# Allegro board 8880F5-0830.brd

Outline 581.66 x 429.26 mm; copper layers: TOP, L02_DGND, L03_SIGNAL, L04_DGND, L05_SIGNAL, L06_DGND, L07_SIGNAL, L08_DGND, L09_SIGNAL, L10_DGND, L11_POWER, L12_DGND, L13_POWER, L14_DGND, L15_POWER, L16_DGND, L17_5V, L18_CBIT, L19_DGND, L20_POWER, L21_DGND, L22_POWER, L23_DGND, L24_POWER, L25_DGND, L26_SIGNAL, L27_DGND, L28_SIGNAL, L29_DGND, L30_SIGNAL, L31_DGND, L32_SIGNAL, L33_DGND, BOTTOM. Coordinates in mm from the lower left corner of the outline.

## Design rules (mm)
net group DIFFPAIR0: nets D31702 D31704
net group DIFFPAIR1: nets D31706 D31708
net group DIFFPAIR2: nets D31710 D31712
net group DIFFPAIR3: nets D31714 D31716
net group DIFFPAIR4: nets D32102 D32104
net group DIFFPAIR5: nets D32106 D32108
net group DIFFPAIR6: nets D32110 D32112
net group DIFFPAIR7: nets D32114 D32116
net group DIFFPAIR8: nets D30102 D30104
net group DIFFPAIR9: nets D30106 D30108
net group DIFFPAIR10: nets D30110 D30112
net group DIFFPAIR11: nets D30114 D30116
net group DIFFPAIR12: nets D30502 D30504
net group DIFFPAIR13: nets D30506 D30508
net group DIFFPAIR14: nets D30510 D30512
net group DIFFPAIR15: nets D30514 D30516

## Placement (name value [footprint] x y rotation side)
BD29  BD120-3A-S8  [FB0805]  129.54 134.62 180 bottom
BD30  BD120-3A-S8  [FB0805]  129.54 146.05 180 bottom
BD31  BD120-3A-S8  [FB0805]  129.54 142.24 0 bottom
BD32  BD120-3A-S8  [FB0805]  513.08 238.76 180 bottom
BD33  BD120-3A-S8  [FB0805]  513.08 242.57 180 bottom
BD34  BD120-3A-S8  [FB0805]  453.64 145.54 0 bottom
BD35  BD120-3A-S8  [FB0805]  453.64 137.92 180 bottom
BD36  BD120-3A-S8  [FB0805]  129.54 138.43 180 bottom
BD37  BD120-3A-S8  [FB0805]  453.64 130.3 180 bottom
BD38  BD120-3A-S8  [FB0805]  513.08 242.57 180 bottom
BD39  BD120-3A-S8  [FB0805]  453.64 141.73 0 bottom
BD40  BD120-3A-S8  [FB0805]  453.64 134.11 180 bottom
BD41  BD120-3A-S8  [FB0805]  513.08 234.95 180 bottom
BD42  BD120-3A-S8  [FB0805]  513.08 231.14 180 bottom
BD43  BD120-3A-S8  [FB0805]  513.08 227.33 180 bottom
BD44  BD120-3A-S8  [FB0805]  129.54 149.86 180 bottom
BR902  330-1-S4  [R0402]  36.83 133.35 270 bottom
C3  0.1U-16-X-S4-MU  [C0402]  184.15 132.33 180 bottom
C4  0.1U-16-X-S4-MU  [C0402]  181.61 132.33 180 bottom
C5  22P-50-N-S4-AVX  [C0402]  221.21 277.48 90 bottom
C6  22P-50-N-S4-AVX  [C0402]  221.21 271.16 270 bottom
C7  0.1U-16-X-S4-MU  [C0402]  110.74 230.12 0 bottom
C8  0.1U-16-X-S4-MU  [C0402]  104.14 215.5 180 bottom
C9  0.1U-16-X-S4-MU  [C0402]  104.24 229.1 180 bottom
CA1  NC/10U-10-X6S-S6-MU  [C0603]  186.05 292.1 0 bottom
CA2  NC/47U-10-X5R-S8-TDK  [C0805]  186.16 294 0 bottom
CA3  NC/10U-10-X6S-S6-MU  [C0603]  174.62 292.1 180 bottom
CA4  NC/47U-10-X5R-S8-TDK  [C0805]  174.52 294 180 bottom
CA5  NC/10U-10-X6S-S6-MU  [C0603]  117.47 290.83 180 bottom
CA6  NC/47U-10-X5R-S8-TDK  [C0805]  117.37 292.74 180 bottom
CA7  NC/10U-10-X6S-S6-MU  [C0603]  169.54 292.1 0 bottom
CA8  NC/47U-10-X5R-S8-TDK  [C0805]  169.65 294 0 bottom
CA9  NC/10U-10-X6S-S6-MU  [C0603]  158.11 292.1 180 bottom
CA10  NC/47U-10-X5R-S8-TDK  [C0805]  158.01 294 180 bottom
CA11  NC/10U-10-X6S-S6-MU  [C0603]  186.05 275.59 0 bottom
CA12  NC/47U-10-X5R-S8-TDK  [C0805]  186.16 277.5 0 bottom
CA13  NC/47U-10-X5R-S8-TDK  [C0805]  202.16 294 0 bottom
CA14  NC/10U-10-X6S-S6-MU  [C0603]  202.06 292.1 0 bottom
CA15  NC/47U-10-X5R-S8-TDK  [C0805]  190.53 294 180 bottom
CA16  NC/10U-10-X6S-S6-MU  [C0603]  190.63 292.1 180 bottom
CA17  NC/47U-10-X5R-S8-TDK  [C0805]  169.65 277.5 0 bottom
CA18  NC/10U-10-X6S-S6-MU  [C0603]  169.54 275.59 0 bottom
CA19  NC/47U-10-X5R-S8-TDK  [C0805]  100.34 249.52 180 bottom
CA20  NC/10U-10-X6S-S6-MU  [C0603]  100.44 247.61 180 bottom
CA21  10U-10-X6S-S6-MU  [C0603]  186.05 289.56 0 bottom
CA22  10U-10-X6S-S6-MU  [C0603]  174.62 289.56 180 bottom
CA23  10U-10-X6S-S6-MU  [C0603]  117.47 288.29 180 bottom
CA24  10U-10-X6S-S6-MU  [C0603]  169.54 289.56 0 bottom
CA25  10U-10-X6S-S6-MU  [C0603]  158.11 289.56 180 bottom
CA26  10U-10-X6S-S6-MU  [C0603]  186.05 273.05 0 bottom
CA27  10U-10-X6S-S6-MU  [C0603]  202.06 289.56 0 bottom
CA28  10U-10-X6S-S6-MU  [C0603]  190.63 289.56 180 bottom
CA29  10U-10-X6S-S6-MU  [C0603]  169.54 273.05 0 bottom
CA30  NC/47U-10-X5R-S8-TDK  [C0805]  95.47 249.57 180 bottom
CA31  10U-10-X6S-S6-MU  [C0603]  95.57 247.66 180 bottom
CA32  NC/10U-10-X6S-S6-MU  [C0603]  202.06 275.59 0 bottom
CA33  NC/47U-10-X5R-S8-TDK  [C0805]  202.16 277.5 0 bottom
CA34  10U-10-X6S-S6-MU  [C0603]  202.06 273.05 0 bottom
CA35  NC/10U-10-X6S-S6-MU  [C0603]  174.62 275.59 180 bottom
CA36  NC/47U-10-X5R-S8-TDK  [C0805]  174.52 277.5 180 bottom
CA37  10U-10-X6S-S6-MU  [C0603]  174.62 273.05 180 bottom
CA38  NC/10U-10-X6S-S6-MU  [C0603]  158.11 275.59 180 bottom
CA39  NC/47U-10-X5R-S8-TDK  [C0805]  158.01 277.5 180 bottom
CA40  10U-10-X6S-S6-MU  [C0603]  158.11 273.05 180 bottom
CB1  0.1U-25-X-S6  [C0603]  116.84 130.81 0 bottom
CB2  10U-16-T-SA  [CODE_A]  116.84 128.27 0 bottom
CB3  0.1U-25-X-S6  [C0603]  472.44 130.81 0 bottom
CB4  10U-16-T-SA  [CODE_A]  472.44 128.27 0 bottom
CB5  0.1U-25-X-S6  [C0603]  556.51 300.99 0 bottom
CB6  10U-16-T-SA  [CODE_A]  556.51 298.45 0 bottom
CB7  0.1U-25-X-S6  [C0603]  223.52 298.45 0 bottom
CB8  10U-16-T-SA  [CODE_A]  223.52 295.91 0 bottom
CB9  0.1U-25-X-S6  [C0603]  23.01 130.71 0 bottom
CB10  10U-25-X7R-SA  [C1206]  22.86 128.27 0 bottom
CB11  0.1U-25-X-S6  [C0603]  484.02 130.71 0 bottom
CB12  10U-25-X7R-SA  [C1206]  483.87 128.27 0 bottom
CB13  0.1U-25-X-S6  [C0603]  547.52 300.89 0 bottom
CB14  10U-25-X7R-SA  [C1206]  547.37 298.45 0 bottom
CB15  0.1U-25-X-S6  [C0603]  12.45 262.13 0 bottom
CB16  10U-25-X7R-SA  [C1206]  12.3 259.69 0 bottom
CB19  0.1U-25-X7R-S4-MU  [C0402]  215.9 17.78 180 bottom
CC1  0.47U-10-X6S-S2-TY  [C0201]  237.98 224.12 90 bottom
CC2  4.7U-10-X6T-S4-MU  [C0402]  236.32 222.4 270 bottom
CC4  0.47U-10-X6S-S2-TY  [C0201]  229.81 247.93 0 bottom
CC6  0.47U-10-X6S-S2-TY  [C0201]  250.17 224.12 90 bottom
CC7  0.47U-10-X6S-S2-TY  [C0201]  229.81 246.66 0 bottom
CC8  0.47U-10-X6S-S2-TY  [C0201]  263.63 224.12 90 bottom
CC9  0.47U-10-X6S-S2-TY  [C0201]  254.61 266.16 270 bottom
CC11  0.47U-10-X6S-S2-TY  [C0201]  251.06 224.12 90 bottom
CC13  0.47U-10-X6S-S2-TY  [C0201]  256.77 224.12 90 bottom
CC15  4.7U-2.5-X6S-S2-MU  [C0201]  259.65 264.95 90 bottom
CC16  NC/4.7U-2.5-X6S-S2-MU  [C0201]  271.64 249.5 0 bottom
CC17  4.7U-2.5-X6S-S2-MU  [C0201]  229.81 253.69 0 bottom
CC19  0.47U-10-X6S-S2-TY  [C0201]  252.83 266.16 270 bottom
CC20  4.7U-10-X6T-S4-MU  [C0402]  254.11 267.66 0 bottom
CC22  0.47U-10-X6S-S2-TY  [C0201]  251.05 266.16 270 bottom
CC23  4.7U-10-X6T-S4-MU  [C0402]  250.34 253.09 270 bottom
CC25  0.47U-10-X6S-S2-TY  [C0201]  272.85 245.18 180 bottom
CC26  0.47U-10-X6S-S2-TY  [C0201]  253.72 266.16 270 bottom
CC27  0.47U-10-X6S-S2-TY  [C0201]  272.85 249.5 180 bottom
CC28  0.47U-10-X6S-S2-TY  [C0201]  259.65 266.16 270 bottom
CC29  0.47U-10-X6S-S2-TY  [C0201]  231.03 253.69 180 bottom
CC30  0.47U-10-X6S-S2-TY  [C0201]  229.81 243.41 0 bottom
CC31  0.47U-10-X6S-S2-TY  [C0201]  249.28 224.12 90 bottom
CC32  0.47U-10-X6S-S2-TY  [C0201]  262.36 224.12 90 bottom
CC33  0.47U-10-X6S-S2-TY  [C0201]  272.85 243.91 180 bottom
CC34  0.47U-10-X6S-S2-TY  [C0201]  251.94 266.16 270 bottom
CC35  0.47U-10-X6S-S2-TY  [C0201]  272.85 241.37 180 bottom
CC36  0.47U-10-X6S-S2-TY  [C0201]  272.85 242.64 180 bottom
CC37  0.47U-10-X6S-S2-TY  [C0201]  247.57 264.95 90 bottom
CC38  NC/4.7U-2.5-X6S-S2-MU  [C0201]  247.57 266.16 270 bottom
CC39  0.47U-10-X6S-S2-TY  [C0201]  231.03 249.2 180 bottom
CC40  4.7U-2.5-X6S-S2-MU  [C0201]  258.5 246.67 180 bottom
CC41  4.7U-2.5-X6S-S2-MU  [C0201]  229.81 249.2 0 bottom
CC42  4.7U-2.5-X6S-S2-MU  [C0201]  251.54 253.03 90 bottom
CD1  0.1U-10-X7R-S2-MU  [C0201]  237.98 225.34 270 top
CD3  0.1U-10-X7R-S2-MU  [C0201]  271.64 241.37 0 top
CD4  0.1U-10-X7R-S2-MU  [C0201]  254.61 264.95 90 top
CD5  0.1U-10-X7R-S2-MU  [C0201]  263.63 225.34 270 top
CD6  0.1U-10-X7R-S2-MU  [C0201]  231.03 246.66 180 top
CD7  0.1U-10-X7R-S2-MU  [C0201]  271.64 242.64 0 top
CD8  0.1U-10-X7R-S2-MU  [C0201]  251.06 225.34 270 top
CD9  0.1U-10-X7R-S2-MU  [C0201]  256.77 225.34 270 top
CD10  0.1U-10-X7R-S2-MU  [C0201]  271.64 249.5 0 top
CD11  0.1U-10-X7R-S2-MU  [C0201]  259.65 264.95 90 top
CD12  0.1U-10-X7R-S2-MU  [C0201]  231.03 253.69 180 top
CD13  0.1U-10-X7R-S2-MU  [C0201]  252.83 264.95 90 top
CD14  0.1U-10-X7R-S2-MU  [C0201]  251.05 264.95 90 top
CD15  0.1U-10-X7R-S2-MU  [C0201]  271.64 245.18 0 top
CD16  0.1U-10-X7R-S2-MU  [C0201]  253.72 264.95 90 top
CD17  0.1U-10-X7R-S2-MU  [C0201]  231.03 247.93 180 top
CD18  0.1U-10-X7R-S2-MU  [C0201]  251.94 264.95 90 top
CD19  0.1U-10-X7R-S2-MU  [C0201]  231.03 243.41 180 top
CD20  0.1U-10-X7R-S2-MU  [C0201]  271.64 243.91 0 top
CD21  0.1U-10-X7R-S2-MU  [C0201]  262.36 225.34 270 top
CD22  0.1U-10-X7R-S2-MU  [C0201]  249.28 225.34 270 top
CD23  0.1U-10-X7R-S2-MU  [C0201]  250.17 225.34 270 top
CD24  0.1U-10-X7R-S2-MU  [C0201]  247.57 264.95 90 top
CD25  0.1U-10-X7R-S2-MU  [C0201]  231.03 249.2 180 top
CSDPS225  V93K_CSDPS_DPS32  [PG_VG93K_PF_DPS32_G8D225]  254 331.47 0 top
CSDPS229  V93K_CSDPS_DPS32  [PG_VG93K_PF_DPS32_G8D229]  180.34 331.47 0 top
CSDPS425  V93K_CSDPS_DPS32  [PG_VG93K_PF_DPS32_G8D425]  254 341.63 0 top
CSDPS429  V93K_CSDPS_DPS32  [PG_VG93K_PF_DPS32_G8D429]  180.34 341.63 0 top
D101/D501  V93K_PS1600 HD  [PG_VG93K_F_HSM_G1D101_501_ND]  327.66 97.79 0 top
D102  V93K_CH  [PG_VG93K_F_G1D102]  327.66 77.47 0 top
D103  V93K_CH  [PG_VG93K_F_G1D103]  327.66 57.15 0 top
D104  V93K_CH  [PG_VG93K_F_G1D104]  327.66 36.83 0 top
D105/D505  V93K_PS1600 HD  [PG_VG93K_F_HSM_G1D105_505_ND]  401.32 97.79 0 top
D106  V93K_CH  [PG_VG93K_F_G1D106]  401.32 77.47 0 top
D107  V93K_CH  [PG_VG93K_F_G1D107]  401.32 57.15 0 top
D108  V93K_CH  [PG_VG93K_F_G1D108]  401.32 36.83 0 top
D109  V93K_CH  [PG_VG93K_F_G2D109]  401.32 331.47 0 top
D110  V93K_CH  [PG_VG93K_F_G2D110]  401.32 351.79 0 top
D111  V93K_CH  [PG_VG93K_F_G2D111]  401.32 372.11 0 top
D112  V93K_CH  [PG_VG93K_F_G2D112]  401.32 392.43 0 top
D113  V93K_CH  [PG_VG93K_F_G2D113]  327.66 331.47 0 top
D114  V93K_CH  [PG_VG93K_F_G2D114]  327.66 351.79 0 top
D115  V93K_CH  [PG_VG93K_F_G2D115]  327.66 372.11 0 top
D116  V93K_CH  [PG_VG93K_F_G2D116]  327.66 392.43 0 top
D117/D517  V93K_PS1600 HD  [PG_VG93K_F_HSM_G3D117_517_ND]  180.34 97.79 0 top
D118  V93K_CH  [PG_VG93K_F_G3D118]  180.34 77.47 0 top
D119  V93K_CH  [PG_VG93K_F_G3D119]  180.34 57.15 0 top
D120  V93K_CH  [PG_VG93K_F_G3D120]  180.34 36.83 0 top
D121/D521  V93K_PS1600 HD  [PG_VG93K_F_HSM_G3D121_521_ND]  254 97.79 0 top
D122  V93K_CH  [PG_VG93K_F_G3D122]  254 77.47 0 top
D123  V93K_CH  [PG_VG93K_F_G3D123]  254 57.15 0 top
D124  V93K_CH  [PG_VG93K_F_G3D124]  254 36.83 0 top
D125  V93K_CH  [PG_VG93K_F_G4D125]  33.02 97.79 0 top
D126  V93K_CH  [PG_VG93K_F_G4D126]  33.02 77.47 0 top
D127  V93K_CH  [PG_VG93K_F_G4D127]  33.02 57.15 0 top
D128  V93K_CH  [PG_VG93K_F_G4D128]  33.02 36.83 0 top
D129  V93K_CH  [PG_VG93K_F_G4D129]  106.68 97.79 0 top
D130  V93K_CH  [PG_VG93K_F_G4D130]  106.68 77.47 0 top
D131  V93K_CH  [PG_VG93K_F_G4D131]  106.68 57.15 0 top
D132  V93K_CH  [PG_VG93K_F_G4D132]  106.68 36.83 0 top
D231  V93K_CH  [PG_VG93K_F_G8D231]  180.34 372.11 0 top
D301  V93K_CH  [PG_VG93K_F_G1D301]  327.66 87.63 0 top
D302  V93K_CH  [PG_VG93K_F_G1D302]  327.66 67.31 0 top
D305  V93K_CH  [PG_VG93K_F_G1D305]  401.32 87.63 0 top
D306  V93K_CH  [PG_VG93K_F_G1D306]  401.32 67.31 0 top
D309  V93K_PSSL  [PG_VG93K_F_PSSL_G2D309_ND]  401.32 341.63 0 top
D313  V93K_PSSL  [PG_VG93K_F_PSSL_G2D313_ND]  327.66 341.63 0 top
D317  V93K_CH  [PG_VG93K_F_G3D317]  180.34 87.63 0 top
D318  V93K_CH  [PG_VG93K_F_G3D318]  180.34 67.31 0 top
D321  V93K_CH  [PG_VG93K_F_G3D321]  254 87.63 0 top
D322  V93K_CH  [PG_VG93K_F_G3D322]  254 67.31 0 top
D431  V93K_CH  [PG_VG93K_F_G8D431]  180.34 382.27 0 top
DPS1  V93K_DPS  [PG_VG93K_F_G1DPS1]  401.32 16.51 0 top
DPS2  V93K_DPS  [PG_VG93K_F_G2DPS2]  327.66 412.75 0 top
DPS3  V93K_DPS  [PG_VG93K_F_G3DPS3]  254 16.51 0 top
DPS8  V93K_DPS  [PG_VG93K_F_G8DPS8]  180.34 412.75 0 top
FD1  -  [FD_040_V2]  159.82 131.98 0 top
FD2  -  [FD_040_V2]  423.24 131.98 0 top
FD3  -  [FD_040_V2]  423.24 297.28 0 top
FD4  -  [FD_040_V2]  156.51 297.46 0 top
FD5  -  [FD_040_V2]  159.82 131.98 180 bottom
FD6  -  [FD_040_V2]  423.24 131.98 180 bottom
FD7  -  [FD_040_V2]  423.24 297.28 180 bottom
FD8  -  [FD_040_V2]  156.51 297.46 180 bottom
FD9  -  [FD_040_V2]  570.23 128.27 180 bottom
FD10  -  [FD_040_V2]  570.23 300.99 0 top
FD11  -  [FD_040_V2]  570.23 300.99 180 bottom
FD12  -  [FD_040_V2]  11.43 300.99 0 top
FD13  -  [FD_040_V2]  11.43 300.99 180 bottom
FD14  -  [FD_040_V2]  11.43 127 0 top
FD15  -  [FD_040_V2]  11.43 127 180 bottom
FD16  -  [FD_040_V2]  570.23 128.27 0 top
GND1  TP01  [TP_040_T]  173.57 294 0 top
GND2  TP01  [TP_040_T]  187.11 294 180 top
GND3  TP01  [TP_040_T]  116.42 292.74 0 top
GND4  TP01  [TP_040_T]  157.06 294 0 top
GND5  TP01  [TP_040_T]  170.6 294 180 top
GND6  TP01  [TP_040_T]  173.57 277.5 0 top
GND7  TP01  [TP_040_T]  203.11 294 180 top
GND8  TP01  [TP_040_T]  189.58 294 0 top
GND9  TP01  [TP_040_T]  170.6 277.5 180 top
GND10  TP01  [TP_040_T]  99.36 249.46 0 top
GND11  TP01  [TP_040_T]  94.49 249.52 0 top
GND12  TP01  [TP_040_T]  203.11 277.5 180 top
GND13  TP01  [TP_040_T]  187.11 277.5 180 top
GND14  TP01  [TP_040_T]  157.06 277.5 0 top
HX8880-F05  REF-CODE-CHIP  [CHIP_CODE]  559.05 279.65 0 top
J1  HDR-2X1-M  [JP_2P_100]  110.24 232.41 270 bottom
J2  HDR-3X1-M  [JP_3P_100]  88.76 205.43 90 bottom
J3  HDR-3X1-M  [JP_3P_100]  88.76 219.15 90 bottom
J4  HDR-2X1-M  [JP_2P_100]  96.27 231.39 90 bottom
J5  HDR-2X1-M  [JP_2P_100]  96.27 243.08 90 bottom
JG_220919AA01  REF-CODE-SOCKET  [SOCKET_CODE]  559.05 284.73 0 top
JG_220919AA02  REF-CODE-SOCKET  [SOCKET_CODE]  559.05 287.27 0 top
K1  G6K-2F-RF-T-5V-SPECIAL  [RL_G6K2FRT_8P_5V_GR]  347.73 292.86 0 bottom
K2  G6K-2F-RF-T-5V-SPECIAL  [RL_G6K2FRT_8P_5V_GR]  334.26 292.86 0 bottom
K3  G6K-2F-RF-T-5V-SPECIAL  [RL_G6K2FRT_8P_5V_GR]  320.8 292.86 0 bottom
K4  G6K-2F-RF-T-5V-SPECIAL  [RL_G6K2FRT_8P_5V_GR]  289.56 276.1 180 bottom
K5  G6K-2F-RF-T-5V-SPECIAL  [RL_G6K2FRT_8P_5V_GR]  307.59 292.86 0 bottom
K6  G6K-2F-RF-T-5V-SPECIAL  [RL_G6K2FRT_8P_5V_GR]  294.39 292.86 0 bottom
K7  G6K-2F-RF-T-5V-SPECIAL  [RL_G6K2FRT_8P_5V_GR]  280.92 292.86 0 bottom
K8  G6K-2F-RF-T-5V-SPECIAL  [RL_G6K2FRT_8P_5V_GR]  267.46 292.86 0 bottom
K9  UA2-5NJ-A-V3  [RL_NECUA2_5V_V3]  219.96 235.46 90 bottom
K10  UA2-5NJ-A-V3  [RL_NECUA2_5V_V3]  111.76 237.24 0 bottom
K11  G6K-2F-RF-T-5V-SPECIAL  [RL_G6K2FRT_8P_5V_GR]  254.25 292.86 0 bottom
K12  UA2-5NJ-A-V3  [RL_NECUA2_5V_V3]  219.96 246.89 90 bottom
K13  UA2-5NJ-A-V3  [RL_NECUA2_5V_V3]  123.7 229.62 180 bottom
K14  UA2-5NJ-A-V3  [RL_NECUA2_5V_V3]  112.01 220.73 180 bottom
K15  UA2-5NJ-A-V3  [RL_NECUA2_5V_V3]  123.99 213.19 180 bottom
K16  G6K-2F-RF-T-5V-SPECIAL  [RL_G6K2FRT_8P_5V_GR]  241.05 292.61 180 bottom
K17  G6K-2F-RF-T-5V-SPECIAL  [RL_G6K2FRT_8P_5V_GR]  188.47 260.35 270 bottom
K18  UB2-5NU-B  [RL_NECUB2_5V]  228.45 274.32 0 bottom
K19  UA2-5NJ-A-V3  [RL_NECUA2_5V_V3]  112.01 213.11 180 bottom
K20  UA2-5NJ-A-V3  [RL_NECUA2_5V_V3]  123.95 220.73 180 bottom
K21  G6K-2F-RF-T-5V-SPECIAL  [RL_G6K2FRT_8P_5V_GR]  204.98 260.35 270 bottom
K22  G6K-2F-RF-T-5V-SPECIAL  [RL_G6K2FRT_8P_5V_GR]  205.23 232.92 270 bottom
K23  G6K-2F-RF-T-5V-SPECIAL  [RL_G6K2FRT_8P_5V_GR]  171.7 219.2 270 bottom
K24  G6K-2F-RF-T-5V-SPECIAL  [RL_G6K2FRT_8P_5V_GR]  188.47 232.92 270 bottom
K25  G6K-2F-RF-T-5V-SPECIAL  [RL_G6K2FRT_8P_5V_GR]  205.23 246.63 270 bottom
K26  G6K-2F-RF-T-5V-SPECIAL  [RL_G6K2FRT_8P_5V_GR]  171.7 232.92 270 bottom
K27  G6K-2F-RF-T-5V-SPECIAL  [RL_G6K2FRT_8P_5V_GR]  188.47 246.63 270 bottom
K28  UA2-5NJ-A-V3  [RL_NECUA2_5V_V3]  100.33 237.24 0 bottom
K29  G6K-2F-RF-T-5V-SPECIAL  [RL_G6K2FRT_8P_5V_GR]  171.7 260.35 270 bottom
K30  G6K-2F-RF-T-5V-SPECIAL  [RL_G6K2FRT_8P_5V_GR]  171.7 246.63 270 bottom
K31  EC2-5NJ-A  [RL_NECEC2_10P_5V]  196.34 276.86 90 bottom
K33  NC/UA2-5NJ-A-V3  [RL_NECUA2_5V_V3]  123.7 237.24 180 bottom
K34  EC2-5NJ-A  [RL_NECEC2_10P_5V]  180.34 293.37 90 bottom
K36  EC2-5NJ-A  [RL_NECEC2_10P_5V]  123.19 292.1 90 bottom
K37  EC2-5NJ-A  [RL_NECEC2_10P_5V]  163.83 293.37 90 bottom
K39  EC2-5NJ-A  [RL_NECEC2_10P_5V]  180.34 276.86 90 bottom
K40  EC2-5NJ-A  [RL_NECEC2_10P_5V]  196.34 293.37 90 bottom
K42  EC2-5NJ-A  [RL_NECEC2_10P_5V]  163.83 276.86 90 bottom
K43  G6K-2F-RF-T-5V-SPECIAL  [RL_G6K2FRT_8P_5V_GR]  269.49 276.1 180 bottom
LD902  LDG-2-S8  [LED_0805]  36.83 130.81 90 top
LOGO1  -  [LOGO_KT_KSMT]  538.48 154.94 0 top
LOGO2  LOGO_HX_Himax  [LOGO_HX_HIMAX]  518.16 138.43 0 top
LQFP176-20X20-P0.4  REF-CODE-CHIP  [CHIP_CODE]  559.05 282.19 0 top
NOREF  -  []  248.96 164.74 0 top
NOREF#2  -  []  201.23 190.12 90 top
NOREF#3  -  []  327.25 205.56 0 top
NOREF#4  -  []  167.7 217.55 90 top
NOREF#5  -  []  310.43 248.88 90 top
NOREF#6  -  []  393.19 255.21 90 top
NOREF#7  -  []  263.63 223.82 90 top
NOREF#8  -  []  394.66 290.39 90 top
NOREF#9  -  []  375.73 194.78 90 top
NOREF#10  -  []  420.15 131.34 90 top
NOREF#11  -  []  451.68 186.77 0 top
NOREF#12  -  []  271.34 241.37 0 top
NOREF#13  -  []  252.51 264.35 90 top
NOREF#14  -  []  317.57 209.63 90 top
NOREF#15  -  []  475.04 239.09 0 top
NOREF#16  -  []  368.03 232.6 0 top
NOREF#17  -  []  118.99 166.5 90 top
NOREF#18  -  []  310.43 193.37 90 top
NOREF#19  -  []  201.49 165.4 90 top
NOREF#20  -  []  237.57 209.63 90 top
NOREF#21  -  []  329.6 224.74 90 top
NOREF#22  -  []  250.18 182.88 0 top
NOREF#23  -  []  250.49 224.74 90 top
NOREF#24  -  []  397.57 131.89 0 top
NOREF#25  -  []  306.71 131.64 0 top
NOREF#26  -  []  511.59 276.41 90 top
NOREF#27  -  []  201.23 192.32 90 top
NOREF#28  -  []  388.66 139.89 0 top
NOREF#29  -  []  256.77 165.04 90 top
NOREF#30  -  []  230.43 187.61 90 top
NOREF#31  -  []  339.97 204.35 90 top
NOREF#32  -  []  392.47 240.66 90 top
NOREF#33  -  []  373.68 265.11 0 top
NOREF#34  -  []  201.23 229.07 90 top
NOREF#35  -  []  167.7 161 90 top
NOREF#36  -  []  167.7 138.47 90 top
NOREF#37  -  []  175.7 257.6 90 top
NOREF#38  -  []  260.29 136.46 90 top
NOREF#39  -  []  450.03 210.36 0 top
NOREF#40  -  []  343.63 163.82 90 top
NOREF#41  -  []  318.32 131.64 0 top
NOREF#42  -  []  414.82 297.12 0 top
NOREF#43  -  []  320.83 254.63 0 top
NOREF#44  -  []  407.71 217.61 0 top
NOREF#45  -  []  221.56 242.89 0 top
NOREF#46  -  []  369.63 273.11 0 top
NOREF#47  -  []  327.25 264.35 90 top
NOREF#48  -  []  254.8 296.86 0 top
NOREF#49  -  []  247.25 265.55 0 top
NOREF#50  -  []  404.15 273.11 0 top
NOREF#51  -  []  367.48 242.38 90 top
NOREF#52  -  []  301.56 250.49 0 top
NOREF#53  -  []  192.47 236.67 90 top
NOREF#54  -  []  473.6 162.62 90 top
NOREF#55  -  []  314.92 144.15 90 top
NOREF#56  -  []  342.04 164.74 0 top
NOREF#57  -  []  393.19 287.22 90 top
NOREF#58  -  []  518.38 259.9 90 top
NOREF#59  -  []  318.32 131.64 0 top
NOREF#60  -  []  346.08 296.86 0 top
NOREF#61  -  []  518.38 276.41 90 top
NOREF#62  -  []  471.21 211.76 0 top
NOREF#63  -  []  119.95 222.33 0 top
NOREF#64  -  []  298.13 274.06 90 top
NOREF#65  -  []  253.33 181.33 90 top
NOREF#66  -  []  346.27 130.77 90 top
NOREF#67  -  []  330.49 163.52 90 top
NOREF#68  -  []  182.82 216.47 90 top
NOREF#69  -  []  194.09 214.75 90 top
NOREF#70  -  []  310.43 246.34 0 top
NOREF#71  -  []  94.68 234.24 0 top
NOREF#72  -  []  235.4 289.88 90 top
NOREF#73  -  []  390.34 192.28 0 top
NOREF#74  -  []  310.43 253.37 0 top
NOREF#75  -  []  263.19 135.19 0 top
NOREF#76  -  []  300.36 248.49 0 top
NOREF#77  -  []  184.47 219.75 90 top
NOREF#78  -  []  271.04 249.18 0 top
NOREF#79  -  []  465.45 290.38 90 top
NOREF#80  -  []  385.19 232.85 0 top
NOREF#81  -  []  413.71 148.15 90 top
NOREF#82  -  []  338.11 288.86 0 top
NOREF#83  -  []  381.74 265.11 0 top
NOREF#84  -  []  333.4 264.35 90 top
NOREF#85  -  []  396.55 289.12 0 top
NOREF#86  -  []  424.55 146.88 90 top
NOREF#87  -  []  115.61 191.95 0 top
NOREF#88  -  []  251.62 205.55 0 top
NOREF#89  -  []  118.7 195.7 0 top
NOREF#90  -  []  237.66 224.74 0 top
NOREF#91  -  []  379 272.56 90 top
NOREF#92  -  []  394 217.36 0 top
NOREF#93  -  []  127.55 191.95 90 top
NOREF#94  -  []  383.09 224.85 0 top
NOREF#95  -  []  235.85 296.61 0 top
NOREF#96  -  []  352.25 184.86 90 top
NOREF#97  -  []  282.9 147.38 0 top
NOREF#98  -  []  220.36 248.49 0 top
NOREF#99  -  []  321.82 227.13 90 top
NOREF#100  -  []  251.05 265.86 90 top
NOREF#101  -  []  385.36 194.18 90 top
NOREF#102  -  []  310.41 253.37 90 top
NOREF#103  -  []  230.73 187.93 0 top
NOREF#104  -  []  367.48 225.87 90 top
NOREF#105  -  []  229.21 183.09 0 top
NOREF#106  -  []  239.33 176.03 0 top
NOREF#107  -  []  413.96 182.44 90 top
NOREF#108  -  []  298.13 214.06 0 top
NOREF#109  -  []  355.89 130.17 90 top
NOREF#110  -  []  329.85 224.74 0 top
NOREF#111  -  []  459.28 183.57 90 top
NOREF#112  -  []  330.49 223.52 90 top
NOREF#113  -  []  296.81 275.94 0 top
NOREF#114  -  []  351.34 181.37 0 top
NOREF#115  -  []  415.1 163.64 0 top
NOREF#116  -  []  451.68 239.34 0 top
NOREF#117  -  []  199.33 257.62 90 top
NOREF#118  -  []  201.49 146.18 0 top
NOREF#119  -  []  373.32 181.42 90 top
NOREF#120  -  []  378.33 209.11 0 top
NOREF#121  -  []  369.63 289.12 0 top
NOREF#122  -  []  184.47 165.4 90 top
NOREF#123  -  []  209.23 216.45 90 top
NOREF#124  -  []  251.94 204.65 90 top
NOREF#125  -  []  410.27 257.37 0 top
NOREF#126  -  []  320.42 131.64 0 top
NOREF#127  -  []  249.6 164.74 90 top
NOREF#128  -  []  232.25 271.67 90 top
NOREF#129  -  []  221.56 179.06 0 top
NOREF#130  -  []  188.08 289.11 90 top
NOREF#131  -  []  472.86 174.55 90 top
NOREF#132  -  []  339.65 265.86 90 top
NOREF#133  -  []  175.7 222.95 90 top
NOREF#134  -  []  412.88 131.89 0 top
NOREF#135  -  []  403.99 163.64 0 top
NOREF#136  -  []  461.86 187.32 0 top
NOREF#137  -  []  249.28 223.82 90 top
NOREF#138  -  []  451.68 195.91 0 top
NOREF#139  -  []  415.1 163.64 0 top
NOREF#140  -  []  117.33 247.35 90 top
NOREF#141  -  []  394.66 242.38 90 top
NOREF#142  -  []  413.1 144.98 0 top
NOREF#143  -  []  392.24 199.18 90 top
NOREF#144  -  []  247.78 140.14 0 top
NOREF#145  -  []  254.61 204.65 90 top
NOREF#146  -  []  232.25 211.67 90 top
NOREF#147  -  []  405.51 217.61 0 top
NOREF#148  -  []  332.51 205.56 0 top
NOREF#149  -  []  393.74 131.44 90 top
NOREF#150  -  []  459.28 183.57 0 top
NOREF#151  -  []  253.4 264.35 90 top
NOREF#152  -  []  310.43 188.88 90 top
NOREF#153  -  []  385.93 178.25 0 top
NOREF#154  -  []  331.62 205.56 90 top
NOREF#155  -  []  252.51 265.56 90 top
NOREF#156  -  []  272.25 249.18 90 top
NOREF#157  -  []  219.81 213.69 90 top
NOREF#158  -  []  330.74 224.74 0 top
NOREF#159  -  []  230.73 247.93 0 top
NOREF#160  -  []  367.48 258.38 90 top
NOREF#161  -  []  230.43 193.37 90 top
NOREF#162  -  []  184.47 192.32 90 top
NOREF#163  -  []  309.51 187.93 0 top
NOREF#164  -  []  420.15 131.44 90 top
NOREF#165  -  []  257.09 223.52 90 top
NOREF#166  -  []  217.41 273.24 0 top
NOREF#167  -  []  182.57 199.39 90 top
NOREF#168  -  []  168.69 273.5 90 top
NOREF#169  -  []  251.86 252.43 90 top
NOREF#170  -  []  331.94 265.86 90 top
NOREF#171  -  []  230.43 188.88 0 top
NOREF#172  -  []  330.73 205.56 0 top
NOREF#173  -  []  337.9 246.35 90 top
NOREF#174  -  []  352.24 189.18 90 top
NOREF#175  -  []  167.7 147.28 90 top
NOREF#176  -  []  463.61 179.15 0 top
NOREF#177  -  []  272.24 243.59 90 top
NOREF#178  -  []  319.33 236.03 0 top
NOREF#179  -  []  310.43 243.09 90 top
NOREF#180  -  []  339.33 265.55 0 top
NOREF#181  -  []  184.47 215.35 90 top
NOREF#182  -  []  250.73 205.56 90 top
NOREF#183  -  []  383.09 289.12 0 top
NOREF#184  -  []  343.95 224.74 90 top
NOREF#185  -  []  272.25 249.82 0 top
NOREF#186  -  []  259.65 264.65 90 top
NOREF#187  -  []  408.88 133.16 90 top
NOREF#188  -  []  209.49 168.6 90 top
NOREF#189  -  []  405.93 224.56 90 top
NOREF#190  -  []  332.51 265.56 90 top
NOREF#191  -  []  378.33 257.11 90 top
NOREF#192  -  []  460.93 225.6 90 top
NOREF#193  -  []  226.27 156.63 90 top
NOREF#194  -  []  387.39 297.12 0 top
NOREF#195  -  []  343.98 288.86 0 top
NOREF#196  -  []  250.73 265.56 0 top
NOREF#197  -  []  411.26 163.09 90 top
NOREF#198  -  []  229.51 189.2 0 top
NOREF#199  -  []  385.19 281.11 0 top
NOREF#200  -  []  352.25 242.96 0 top
NOREF#201  -  []  366.88 222.7 0 top
NOREF#202  -  []  404.4 289.17 90 top
NOREF#203  -  []  309.51 189.2 0 top
NOREF#204  -  []  385.19 257.11 0 top
NOREF#205  -  []  352.25 242.32 90 top
NOREF#206  -  []  194.09 146.68 90 top
NOREF#207  -  []  106.76 210.11 90 top
NOREF#208  -  []  404.4 225.16 90 top
NOREF#209  -  []  252.83 204.65 90 top
NOREF#210  -  []  168.13 145.38 90 top
NOREF#211  -  []  182.57 171.96 0 top
NOREF#212  -  []  300.74 286.96 90 top
NOREF#213  -  []  297.71 216.09 0 top
NOREF#214  -  []  310.73 193.69 0 top
NOREF#215  -  []  410.27 257.37 0 top
NOREF#216  -  []  317.66 224.72 0 top
NOREF#217  -  []  407.67 129.99 90 top
NOREF#218  -  []  468.85 259.9 90 top
NOREF#219  -  []  201.23 227.72 0 top
NOREF#220  -  []  253.72 264.65 90 top
NOREF#221  -  []  272.25 242.96 0 top
NOREF#222  -  []  184.47 161 90 top
NOREF#223  -  []  423.45 146.93 90 top
NOREF#224  -  []  256.77 223.82 90 top
NOREF#225  -  []  391.8 217.36 0 top
NOREF#226  -  []  261.63 255.43 90 top
NOREF#227  -  []  471.59 130.36 90 top
NOREF#228  -  []  184.47 145.93 90 top
NOREF#229  -  []  392.21 131.94 90 top
NOREF#230  -  []  329.6 223.52 90 top
NOREF#231  -  []  460.93 182.17 90 top
NOREF#232  -  []  333.4 265.55 0 top
NOREF#233  -  []  412.62 241.11 0 top
NOREF#234  -  []  392.73 171.64 0 top
NOREF#235  -  []  410.84 163.64 90 top
NOREF#236  -  []  66.26 271.33 90 top
NOREF#237  -  []  337.9 186.35 90 top
NOREF#238  -  []  184.47 159.65 0 top
NOREF#239  -  []  390.53 163.64 0 top
NOREF#240  -  []  230.43 188.88 90 top
NOREF#241  -  []  118.74 215.34 0 top
NOREF#242  -  []  182.57 158.5 0 top
NOREF#243  -  []  369.63 273.11 0 top
NOREF#244  -  []  331.62 265.56 90 top
NOREF#245  -  []  248.96 224.72 0 top
NOREF#246  -  []  453.88 239.34 0 top
NOREF#247  -  []  396.55 241.11 0 top
NOREF#248  -  []  331.05 205.86 90 top
NOREF#249  -  []  309.21 248.88 0 top
NOREF#250  -  []  192.47 209.49 90 top
NOREF#251  -  []  230.43 253.37 0 top
NOREF#252  -  []  310.73 193.69 0 top
NOREF#253  -  []  192.57 187.82 90 top
NOREF#254  -  []  177.33 173.86 90 top
NOREF#255  -  []  379.48 255.21 90 top
NOREF#256  -  []  334.61 264.65 90 top
NOREF#257  -  []  167.7 187.92 90 top
NOREF#258  -  []  256.45 224.72 0 top
NOREF#259  -  []  343.95 164.74 90 top
NOREF#260  -  []  369.38 257.11 0 top
NOREF#261  -  []  155.57 291.65 90 top
NOREF#262  -  []  405.5 257.37 90 top
NOREF#263  -  []  329.85 224.72 0 top
NOREF#264  -  []  324.9 288.91 90 top
NOREF#265  -  []  373.83 192.28 0 top
NOREF#266  -  []  201.49 178.86 90 top
NOREF#267  -  []  272.25 245.5 0 top
NOREF#268  -  []  167.7 200.54 90 top
NOREF#269  -  []  485.36 259.9 90 top
NOREF#270  -  []  397.8 163.19 90 top
NOREF#271  -  []  262.36 225.04 90 top
NOREF#272  -  []  315.16 290.13 90 top
NOREF#273  -  []  351.34 241.37 0 top
NOREF#274  -  []  342.36 163.82 90 top
NOREF#275  -  []  309.51 249.2 0 top
NOREF#276  -  []  378.75 256.56 90 top
NOREF#277  -  []  201.49 149.73 90 top
NOREF#278  -  []  201.66 199.99 90 top
NOREF#279  -  []  166.06 243.9 90 top
NOREF#280  -  []  303.84 288.86 0 top
NOREF#281  -  []  478.57 257.36 90 top
NOREF#282  -  []  251.06 163.82 90 top
NOREF#283  -  []  237.98 225.04 90 top
NOREF#284  -  []  271.34 242.64 0 top
NOREF#285  -  []  237.98 163.82 90 top
NOREF#286  -  []  184.47 200.54 90 top
NOREF#287  -  []  368.28 281.11 0 top
NOREF#288  -  []  230.43 186.34 90 top
NOREF#289  -  []  194.09 160.4 90 top
NOREF#290  -  []  272.24 249.18 90 top
NOREF#291  -  []  309.51 253.69 0 top
NOREF#292  -  []  247.25 205.56 0 top
NOREF#293  -  []  382.47 133.16 90 top
NOREF#294  -  []  262.36 165.04 90 top
NOREF#295  -  []  404.15 225.11 0 top
NOREF#296  -  []  224.65 211.67 0 top
NOREF#297  -  []  184.47 206.29 90 top
NOREF#298  -  []  182.57 199.39 0 top
NOREF#299  -  []  460.93 210.36 90 top
NOREF#300  -  []  451.68 186.77 0 top
NOREF#301  -  []  104.18 191.95 0 top
NOREF#302  -  []  124.1 238.84 0 top
NOREF#303  -  []  167.7 190.12 90 top
NOREF#304  -  []  230.73 189.2 0 top
NOREF#305  -  []  252.83 264.65 90 top
NOREF#306  -  []  263.63 165.04 90 top
NOREF#307  -  []  473.79 239.64 0 top
NOREF#308  -  []  346.27 135.17 90 top
NOREF#309  -  []  334.29 264.35 90 top
NOREF#310  -  []  406.65 223.21 90 top
NOREF#311  -  []  201.23 200.54 0 top
NOREF#312  -  []  397.8 163.09 90 top
NOREF#313  -  []  308.36 202.16 45 top
NOREF#314  -  []  127.95 195.15 0 top
NOREF#315  -  []  451.68 214.96 0 top
NOREF#316  -  []  383.83 194.68 90 top
NOREF#317  -  []  373.93 297.12 0 top
NOREF#318  -  []  411.99 178.25 90 top
NOREF#319  -  []  230.41 248.88 90 top
NOREF#320  -  []  167.7 173.11 90 top
NOREF#321  -  []  392.47 272.66 90 top
NOREF#322  -  []  260.83 234.63 90 top
NOREF#323  -  []  230.41 243.09 90 top
NOREF#324  -  []  465.81 171.53 0 top
NOREF#325  -  []  398.65 265.37 0 top
NOREF#326  -  []  287.27 286.96 90 top
NOREF#327  -  []  473.79 234.49 90 top
NOREF#328  -  []  399.8 207.46 90 top
NOREF#329  -  []  251.22 253.63 0 top
NOREF#330  -  []  461.96 166.93 0 top
NOREF#331  -  []  412.62 249.11 0 top
NOREF#332  -  []  271.34 189.5 0 top
NOREF#333  -  []  279.27 288.86 0 top
NOREF#334  -  []  319.15 296.86 0 top
NOREF#335  -  []  410.52 241.11 0 top
NOREF#336  -  []  175.7 182.06 90 top
NOREF#337  -  []  223.56 185.29 90 top
NOREF#338  -  []  250.17 223.82 90 top
NOREF#339  -  []  320.42 139.64 0 top
NOREF#340  -  []  301.56 182.89 0 top
NOREF#341  -  []  264.29 272.1 90 top
NOREF#342  -  []  230.83 164.63 0 top
NOREF#343  -  []  310.73 247.93 0 top
NOREF#344  -  []  339.89 288.41 90 top
NOREF#345  -  []  386.53 181.42 90 top
NOREF#346  -  []  351.04 242.96 0 top
NOREF#347  -  []  272.25 243.59 90 top
NOREF#348  -  []  93.76 273.87 90 top
NOREF#349  -  []  209.49 150.83 90 top
NOREF#350  -  []  377.32 188.15 0 top
NOREF#351  -  []  390.94 273.16 90 top
NOREF#352  -  []  199.08 254 90 top
NOREF#353  -  []  390.69 289.12 0 top
NOREF#354  -  []  259.33 265.56 90 top
NOREF#355  -  []  352.25 244.23 0 top
NOREF#356  -  []  298.16 177.06 0 top
NOREF#357  -  []  331.86 192.43 90 top
NOREF#358  -  []  331.22 193.63 0 top
NOREF#359  -  []  182.57 212.85 90 top
NOREF#360  -  []  485.36 292.02 90 top
NOREF#361  -  []  472.86 210.36 90 top
NOREF#362  -  []  415.6 146.88 0 top
NOREF#363  -  []  408.63 242.38 90 top
NOREF#364  -  []  459.28 227 0 top
NOREF#365  -  []  165.8 254 0 top
NOREF#366  -  []  310.43 186.34 0 top
NOREF#367  -  []  312.42 146.05 0 top
NOREF#368  -  []  107.76 238.84 0 top
NOREF#369  -  []  238.45 197.01 0 top
NOREF#370  -  []  419.4 171.64 0 top
NOREF#371  -  []  210.86 187.32 90 top
NOREF#372  -  []  405.51 209.61 0 top
NOREF#373  -  []  379.52 171.39 0 top
NOREF#374  -  []  263.95 164.74 90 top
NOREF#375  -  []  310.43 188.88 0 top
NOREF#376  -  []  420.62 287.22 90 top
NOREF#377  -  []  413.2 164.91 90 top
NOREF#378  -  []  318.3 163.52 90 top
NOREF#379  -  []  229.05 211.67 0 top
NOREF#380  -  []  257.08 132.19 90 top
NOREF#381  -  []  225.83 204.31 0 top
NOREF#382  -  []  386.46 131.89 0 top
NOREF#383  -  []  348.28 296.86 0 top
NOREF#384  -  []  175.7 150.58 90 top
NOREF#385  -  []  185.2 273.5 90 top
NOREF#386  -  []  271.56 134.74 90 top
NOREF#387  -  []  184.47 186.57 0 top
NOREF#388  -  []  208.98 257.6 90 top
NOREF#389  -  []  332.83 205.86 90 top
NOREF#390  -  []  306.71 139.64 0 top
NOREF#391  -  []  313.22 288.41 90 top
NOREF#392  -  []  194.09 255.9 90 top
NOREF#393  -  []  251.06 165.04 90 top
NOREF#394  -  []  300.36 237.06 0 top
NOREF#395  -  []  167.7 151.68 90 top
NOREF#396  -  []  339.89 288.31 90 top
NOREF#397  -  []  327.57 264.65 90 top
NOREF#398  -  []  192.47 259.8 90 top
NOREF#399  -  []  167.7 151.68 90 top
NOREF#400  -  []  463.61 222.58 0 top
NOREF#401  -  []  167.7 174.46 90 top
NOREF#402  -  []  344.62 131.89 90 top
NOREF#403  -  []  201.23 192.32 90 top
NOREF#404  -  []  209.49 175.56 90 top
NOREF#405  -  []  419.47 241.11 90 top
NOREF#406  -  []  226.85 211.67 0 top
NOREF#407  -  []  245.15 288.66 90 top
NOREF#408  -  []  273.95 155.38 0 top
NOREF#409  -  []  261.21 286.96 0 top
NOREF#410  -  []  165.8 131.57 90 top
NOREF#411  -  []  237.66 164.74 0 top
NOREF#412  -  []  459.24 219.3 0 top
NOREF#413  -  []  84.04 287.84 90 top
NOREF#414  -  []  250.73 265.56 90 top
NOREF#415  -  []  113.08 129.54 0 top
NOREF#416  -  []  122.41 178.64 0 top
NOREF#417  -  []  167.7 149.48 90 top
NOREF#418  -  []  379.48 222.7 90 top
NOREF#419  -  []  192.57 147.18 90 top
NOREF#420  -  []  346.69 128.87 90 top
NOREF#421  -  []  230.41 187.61 90 top
NOREF#422  -  []  209.59 147.43 90 top
NOREF#423  -  []  371.48 232.6 0 top
NOREF#424  -  []  461.96 217.98 0 top
NOREF#425  -  []  119.7 238.84 0 top
NOREF#426  -  []  238.45 257.01 0 top
NOREF#427  -  []  313.22 288.31 90 top
NOREF#428  -  []  201.49 178.86 90 top
NOREF#429  -  []  106.76 217.73 90 top
NOREF#430  -  []  383.83 209.11 0 top
NOREF#431  -  []  200.98 258.7 90 top
NOREF#432  -  []  333.72 204.65 90 top
NOREF#433  -  []  302.11 129.74 0 top
NOREF#434  -  []  482.64 192.46 90 top
NOREF#435  -  []  167.7 229.07 90 top
NOREF#436  -  []  237.98 223.82 90 top
NOREF#437  -  []  118.7 182.93 90 top
NOREF#438  -  []  400.34 194.68 90 top
NOREF#439  -  []  311.15 159.63 90 top
NOREF#440  -  []  272.55 182.64 0 top
NOREF#441  -  []  310.73 249.2 0 top
NOREF#442  -  []  272.24 249.18 90 top
NOREF#443  -  []  192.47 246.08 90 top
NOREF#444  -  []  328.96 164.72 0 top
NOREF#445  -  []  351.34 242.64 0 top
NOREF#446  -  []  397.57 131.89 0 top
NOREF#447  -  []  317.05 288.86 0 top
NOREF#448  -  []  247.57 204.65 90 top
NOREF#449  -  []  209.23 195.52 90 top
NOREF#450  -  []  331.38 164.74 90 top
NOREF#451  -  []  175.7 264.1 90 top
NOREF#452  -  []  528.1 259.9 90 top
NOREF#453  -  []  555.66 300.54 90 top
NOREF#454  -  []  468.01 214.96 0 top
NOREF#455  -  []  240.5 288.61 0 top
NOREF#456  -  []  209.33 242.68 90 top
NOREF#457  -  []  413.71 178.82 0 top
NOREF#458  -  []  106.29 174.19 90 top
NOREF#459  -  []  184.47 227.72 90 top
NOREF#460  -  []  450.03 234.74 0 top
NOREF#461  -  []  473.6 206.05 90 top
NOREF#462  -  []  481.96 276.41 90 top
NOREF#463  -  []  415.08 139.89 0 top
NOREF#464  -  []  379.01 288.67 90 top
NOREF#465  -  []  383.09 273.11 0 top
NOREF#466  -  []  120.24 171.1 0 top
NOREF#467  -  []  409.49 163.64 0 top
NOREF#468  -  []  344.37 128.27 0 top
NOREF#469  -  []  366.88 255.21 0 top
NOREF#470  -  []  351.04 185.5 0 top
NOREF#471  -  []  192.47 218.65 90 top
NOREF#472  -  []  408.92 265.37 0 top
NOREF#473  -  []  397.57 131.89 0 top
NOREF#474  -  []  339.33 264.35 90 top
NOREF#475  -  []  238.3 224.74 90 top
NOREF#476  -  []  252.51 205.56 0 top
NOREF#477  -  []  175.8 147.18 90 top
NOREF#478  -  []  275.12 271.65 90 top
NOREF#479  -  []  175.8 242.68 90 top
NOREF#480  -  []  342.04 224.74 0 top
NOREF#481  -  []  112.41 195.15 0 top
NOREF#482  -  []  450.03 225.6 0 top
NOREF#483  -  []  115.87 167.82 90 top
NOREF#484  -  []  184.47 227.72 0 top
NOREF#485  -  []  118.7 188.08 0 top
NOREF#486  -  []  106.11 234.24 0 top
NOREF#487  -  []  230.43 243.09 0 top
NOREF#488  -  []  192.47 195.52 90 top
NOREF#489  -  []  366.88 239.21 0 top
NOREF#490  -  []  96.58 195.15 0 top
NOREF#491  -  []  100.73 238.84 0 top
NOREF#492  -  []  271.04 181.69 0 top
NOREF#493  -  []  400.85 233.11 0 top
NOREF#494  -  []  192.47 264.1 90 top
NOREF#495  -  []  167.7 241.43 90 top
NOREF#496  -  []  167.7 186.57 90 top
NOREF#497  -  []  226.83 269.63 90 top
NOREF#498  -  []  242.23 233.13 0 top
NOREF#499  -  []  166.06 162.12 90 top
NOREF#500  -  []  396.55 273.11 0 top
NOREF#501  -  []  465.45 276.41 90 top
NOREF#502  -  []  271.04 189.18 0 top
NOREF#503  -  []  167.7 201.89 90 top
NOREF#504  -  []  471.21 219.38 0 top
NOREF#505  -  []  221.56 231.46 0 top
NOREF#506  -  []  310.43 248.88 0 top
NOREF#507  -  []  192.57 228.97 90 top
NOREF#508  -  []  330.17 163.82 90 top
NOREF#509  -  []  103.93 235.64 90 top
NOREF#510  -  []  230.43 253.37 90 top
NOREF#511  -  []  167.7 233.47 90 top
NOREF#512  -  []  394.66 226.38 90 top
NOREF#513  -  []  330.73 264.35 90 top
NOREF#514  -  []  368.03 249.11 0 top
NOREF#515  -  []  308.36 262.16 45 top
NOREF#516  -  []  115.61 191.95 90 top
NOREF#517  -  []  338.2 246.67 0 top
NOREF#518  -  []  230.41 186.34 90 top
NOREF#519  -  []  295.96 237.06 0 top
NOREF#520  -  []  461.96 174.55 0 top
NOREF#521  -  []  312.79 288.86 90 top
NOREF#522  -  []  253.33 241.33 90 top
NOREF#523  -  []  409.17 281.37 0 top
NOREF#524  -  []  299.81 273.69 90 top
NOREF#525  -  []  182.82 148.4 90 top
NOREF#526  -  []  331.05 265.86 90 top
NOREF#527  -  []  309.21 253.37 0 top
NOREF#528  -  []  315.82 129.74 0 top
NOREF#529  -  []  230.43 254.01 0 top
NOREF#530  -  []  272.24 242.32 90 top
NOREF#531  -  []  383.09 224.85 0 top
NOREF#532  -  []  346.27 135.17 90 top
NOREF#533  -  []  229.21 243.09 0 top
NOREF#534  -  []  199.59 230.19 90 top
NOREF#535  -  []  272.55 183.91 0 top
NOREF#536  -  []  184.47 255.15 0 top
NOREF#537  -  []  250.74 164.74 0 top
NOREF#538  -  []  303.56 245.29 90 top
NOREF#539  -  []  209.49 162.1 90 top
NOREF#540  -  []  465.81 214.96 0 top
NOREF#541  -  []  103.93 235.64 0 top
NOREF#542  -  []  331.38 223.52 90 top
NOREF#543  -  []  237.66 224.72 0 top
NOREF#544  -  []  118.7 195.7 0 top
NOREF#545  -  []  210.86 214.75 90 top
NOREF#546  -  []  254.29 205.56 0 top
NOREF#547  -  []  418.12 273.37 0 top
NOREF#548  -  []  201.23 186.57 0 top
NOREF#549  -  []  277.17 288.86 0 top
NOREF#550  -  []  238.3 163.52 90 top
NOREF#551  -  []  385.19 249.11 0 top
NOREF#552  -  []  411.09 146.88 90 top
NOREF#553  -  []  392.47 240.56 90 top
NOREF#554  -  []  406.65 287.22 90 top
NOREF#555  -  []  286.12 288.86 90 top
NOREF#556  -  []  342.68 223.52 90 top
NOREF#557  -  []  167.7 214 90 top
NOREF#558  -  []  168.13 240.88 90 top
NOREF#559  -  []  167.7 132.72 0 top
NOREF#560  -  []  459.28 168.33 90 top
NOREF#561  -  []  247.25 205.55 0 top
NOREF#562  -  []  247.78 132.14 90 top
NOREF#563  -  []  495.08 257.36 90 top
NOREF#564  -  []  375.22 180.15 0 top
NOREF#565  -  []  528.1 257.36 90 top
NOREF#566  -  []  253.53 140.14 0 top
NOREF#567  -  []  471.21 168.33 90 top
NOREF#568  -  []  387.8 210.63 90 top
NOREF#569  -  []  238.3 223.52 90 top
NOREF#570  -  []  246.23 233.13 0 top
NOREF#571  -  []  192.57 160.9 90 top
NOREF#572  -  []  333.4 265.56 90 top
NOREF#573  -  []  393.31 131.89 90 top
NOREF#574  -  []  309.21 187.61 0 top
NOREF#575  -  []  367.13 271.21 0 top
NOREF#576  -  []  332.61 296.86 0 top
NOREF#577  -  []  383.09 289.12 0 top
NOREF#578  -  []  352.24 189.18 90 top
NOREF#579  -  []  392.47 224.4 90 top
NOREF#580  -  []  240.83 194.63 0 top
NOREF#581  -  []  209.49 148.63 90 top
NOREF#582  -  []  284.79 272.65 90 top
NOREF#583  -  []  471.21 175.95 90 top
NOREF#584  -  []  375.73 196.98 90 top
NOREF#585  -  []  265.64 280.1 0 top
NOREF#586  -  []  112.05 246.78 90 top
NOREF#587  -  []  182.57 240.28 0 top
NOREF#588  -  []  271.34 183.91 0 top
NOREF#589  -  []  271.04 242.96 0 top
NOREF#590  -  []  390.53 188.15 0 top
NOREF#591  -  []  453.88 195.91 0 top
NOREF#592  -  []  166.06 135.19 90 top
NOREF#593  -  []  263.14 282 0 top
NOREF#594  -  []  118.33 273.87 90 top
NOREF#595  -  []  309.51 193.69 0 top
NOREF#596  -  []  354.27 131.87 90 top
NOREF#597  -  []  399.67 131.89 0 top
NOREF#598  -  []  378.33 224.6 90 top
NOREF#599  -  []  396.55 225.11 0 top
NOREF#600  -  []  401.89 163.64 0 top
NOREF#601  -  []  262.36 296.86 0 top
NOREF#602  -  []  339.33 205.56 0 top
NOREF#603  -  []  351.34 245.18 0 top
NOREF#604  -  []  337.09 163.52 90 top
NOREF#605  -  []  459.28 227 90 top
NOREF#606  -  []  405.5 273.11 90 top
NOREF#607  -  []  119.95 222.33 0 top
NOREF#608  -  []  423.2 146.88 0 top
NOREF#609  -  []  420.62 239.21 90 top
NOREF#610  -  []  376.98 224.6 0 top
NOREF#611  -  []  336.45 224.74 0 top
NOREF#612  -  []  312.46 131.69 90 top
NOREF#613  -  []  230.43 246.34 0 top
NOREF#614  -  []  284.77 288.86 0 top
NOREF#615  -  []  218.13 274.06 90 top
NOREF#616  -  []  253.72 265.86 90 top
NOREF#617  -  []  120.21 178.64 0 top
NOREF#618  -  []  258.1 288.86 0 top
NOREF#619  -  []  309.21 186.34 0 top
NOREF#620  -  []  302.11 180.71 0 top
NOREF#621  -  []  119.7 231.22 0 top
NOREF#622  -  []  259.65 204.65 90 top
NOREF#623  -  []  182.57 240.28 90 top
NOREF#624  -  []  221.56 250.49 0 top
NOREF#625  -  []  256.77 225.04 90 top
NOREF#626  -  []  290.11 280.1 0 top
NOREF#627  -  []  511.59 259.9 90 top
NOREF#628  -  []  241.6 296.61 0 top
NOREF#629  -  []  334.29 205.56 0 top
NOREF#630  -  []  266.74 272.1 0 top
NOREF#631  -  []  275.3 155.38 0 top
NOREF#632  -  []  383.01 139.89 0 top
NOREF#633  -  []  246.23 173.13 0 top
NOREF#634  -  []  108.27 178.64 0 top
NOREF#635  -  []  182.82 257.62 90 top
NOREF#636  -  []  385.32 178.25 90 top
NOREF#637  -  []  298.24 288.86 0 top
NOREF#638  -  []  209.23 202.99 90 top
NOREF#639  -  []  415.61 179.97 90 top
NOREF#640  -  []  342.36 165.04 90 top
NOREF#641  -  []  352.93 288.86 90 top
NOREF#642  -  []  199.59 243.9 90 top
NOREF#643  -  []  310.73 253.69 0 top
NOREF#644  -  []  208.98 264.1 90 top
NOREF#645  -  []  328.96 164.74 0 top
NOREF#646  -  []  218.16 248.49 0 top
NOREF#647  -  []  301.95 290.13 90 top
NOREF#648  -  []  251.38 163.52 90 top
NOREF#649  -  []  351.04 184.23 0 top
NOREF#650  -  []  390.53 146.88 0 top
NOREF#651  -  []  192.47 164.3 90 top
NOREF#652  -  []  250.23 132.14 0 top
NOREF#653  -  []  175.7 162.1 90 top
NOREF#654  -  []  253.72 205.86 90 top
NOREF#655  -  []  388.35 217.36 0 top
NOREF#656  -  []  192.57 256.4 90 top
NOREF#657  -  []  209.23 232.37 90 top
NOREF#658  -  []  388.43 180.15 0 top
NOREF#659  -  []  352.25 241.69 0 top
NOREF#660  -  []  485.36 257.36 90 top
NOREF#661  -  []  209.49 164.3 90 top
NOREF#662  -  []  422.95 163.69 90 top
NOREF#663  -  []  111.54 290.38 90 top
NOREF#664  -  []  297.41 213.24 0 top
NOREF#665  -  []  166.06 203.01 90 top
NOREF#666  -  []  351.04 244.23 0 top
NOREF#667  -  []  395.67 133.16 90 top
NOREF#668  -  []  317.05 288.86 0 top
NOREF#669  -  []  352.55 249.5 0 top
NOREF#670  -  []  184.47 233.47 90 top
NOREF#671  -  []  201.49 151.93 90 top
NOREF#672  -  []  318.3 223.52 90 top
NOREF#673  -  []  336.77 163.82 90 top
NOREF#674  -  []  336.45 224.72 0 top
NOREF#675  -  []  127.3 235.64 90 top
NOREF#676  -  []  327.57 264.65 90 top
NOREF#677  -  []  192.47 222.95 90 top
NOREF#678  -  []  210.6 255.9 90 top
NOREF#679  -  []  168.13 227.17 90 top
NOREF#680  -  []  247.34 133.41 90 top
NOREF#681  -  []  374.34 210.38 90 top
NOREF#682  -  []  293.31 272.1 0 top
NOREF#683  -  []  119.99 214.79 0 top
NOREF#684  -  []  396.55 225.11 0 top
NOREF#685  -  []  247.25 265.55 0 top
NOREF#686  -  []  312.25 271.67 90 top
NOREF#687  -  []  175.7 216.45 90 top
NOREF#688  -  []  272.24 183.59 90 top
NOREF#689  -  []  254.29 265.55 0 top
NOREF#690  -  []  167.7 258.7 90 top
NOREF#691  -  []  381.2 242.38 90 top
NOREF#692  -  []  385.19 241.11 0 top
NOREF#693  -  []  177.33 187.32 90 top
NOREF#694  -  []  201.49 165.4 90 top
NOREF#695  -  []  209.23 230.17 90 top
NOREF#696  -  []  209.23 218.65 90 top
NOREF#697  -  []  201.49 163.2 90 top
NOREF#698  -  []  199.59 203.01 90 top
NOREF#699  -  []  262.04 224.72 0 top
NOREF#700  -  []  209.33 215.25 90 top
NOREF#701  -  []  101.82 273.87 90 top
NOREF#702  -  []  373.83 192.28 90 top
NOREF#703  -  []  272.25 244.86 90 top
NOREF#704  -  []  392.73 154.88 0 top
NOREF#705  -  []  420.62 271.47 90 top
NOREF#706  -  []  269.69 135.19 0 top
NOREF#707  -  []  221.56 239.06 0 top
NOREF#708  -  []  377.48 273.16 90 top
NOREF#709  -  []  35.83 132.61 0 top
NOREF#710  -  []  230.43 189.52 0 top
NOREF#711  -  []  230.43 248.88 90 top
NOREF#712  -  []  201.23 201.89 90 top
NOREF#713  -  []  342.68 164.74 90 top
NOREF#714  -  []  304.61 131.64 0 top
NOREF#715  -  []  318.45 257.01 0 top
NOREF#716  -  []  411.52 146.43 90 top
NOREF#717  -  []  93.02 247.21 90 top
NOREF#718  -  []  254.29 205.55 0 top
NOREF#719  -  []  301.56 242.89 0 top
NOREF#720  -  []  343.2 172.26 90 top
NOREF#721  -  []  495.08 277.31 90 top
NOREF#722  -  []  336.77 165.04 90 top
NOREF#723  -  []  112.41 214.71 0 top
NOREF#724  -  []  405.5 241.11 90 top
NOREF#725  -  []  310.43 193.37 0 top
NOREF#726  -  []  329.28 223.82 90 top
NOREF#727  -  []  296.96 192.14 0 top
NOREF#728  -  []  192.47 148.38 90 top
NOREF#729  -  []  339.33 265.56 90 top
NOREF#730  -  []  229.51 186.66 0 top
NOREF#731  -  []  201.23 247.18 90 top
NOREF#732  -  []  406.52 131.89 90 top
NOREF#733  -  []  177.33 214.75 90 top
NOREF#734  -  []  411.26 209.66 90 top
NOREF#735  -  []  310.73 253.69 0 top
NOREF#736  -  []  192.47 175.56 90 top
NOREF#737  -  []  374.08 195.9 90 top
NOREF#738  -  []  367.73 290.39 90 top
NOREF#739  -  []  380.59 222.95 0 top
NOREF#740  -  []  396.55 273.11 0 top
NOREF#741  -  []  215.96 177.06 0 top
NOREF#742  -  []  331.62 264.35 90 top
NOREF#743  -  []  119.99 214.79 0 top
NOREF#744  -  []  401.87 194.18 90 top
NOREF#745  -  []  404.4 257.42 90 top
NOREF#746  -  []  107.76 238.84 0 top
NOREF#747  -  []  182.57 158.5 90 top
NOREF#748  -  []  330.51 288.86 0 top
NOREF#749  -  []  230.73 193.69 0 top
NOREF#750  -  []  320.94 151.63 90 top
NOREF#751  -  []  303.84 288.86 0 top
NOREF#752  -  []  381.74 249.11 0 top
NOREF#753  -  []  192.57 174.36 90 top
NOREF#754  -  []  448.94 273.87 90 top
NOREF#755  -  []  334.61 265.86 90 top
NOREF#756  -  []  165.8 158.5 0 top
NOREF#757  -  []  332.51 205.55 0 top
NOREF#758  -  []  118.33 289.48 90 top
NOREF#759  -  []  201.23 219.75 90 top
NOREF#760  -  []  316.97 139.64 0 top
NOREF#761  -  []  411.52 146.33 90 top
NOREF#762  -  []  165.8 199.39 90 top
NOREF#763  -  []  391.96 131.89 0 top
NOREF#764  -  []  383.09 241.11 0 top
NOREF#765  -  []  331.62 265.55 0 top
NOREF#766  -  []  399.39 161.74 0 top
NOREF#767  -  []  352.25 241.05 90 top
NOREF#768  -  []  343.31 164.74 0 top
NOREF#769  -  []  343.83 171.63 90 top
NOREF#770  -  []  251.38 224.74 90 top
NOREF#771  -  []  416.03 179.42 90 top
NOREF#772  -  []  340.83 234.63 90 top
NOREF#773  -  []  310.43 249.52 0 top
NOREF#774  -  []  470.79 128.27 0 top
NOREF#775  -  []  371.48 265.11 0 top
NOREF#776  -  []  410.52 289.12 0 top
NOREF#777  -  []  118.45 239.39 0 top
NOREF#778  -  []  459.28 192.71 0 top
NOREF#779  -  []  192.47 202.99 90 top
NOREF#780  -  []  237.98 165.04 90 top
NOREF#781  -  []  388.43 163.64 0 top
NOREF#782  -  []  399.99 164.91 90 top
NOREF#783  -  []  272.25 182.96 0 top
NOREF#784  -  []  105.83 190.55 90 top
NOREF#785  -  []  310.41 243.09 90 top
NOREF#786  -  []  301.56 179.06 0 top
NOREF#787  -  []  192.47 150.58 90 top
NOREF#788  -  []  392.47 256.56 90 top
NOREF#789  -  []  327.89 204.35 90 top
NOREF#790  -  []  397.8 146.43 90 top
NOREF#791  -  []  303.15 211.32 90 top
NOREF#792  -  []  327.25 205.56 90 top
NOREF#793  -  []  165.8 185.42 90 top
NOREF#794  -  []  251.62 265.56 90 top
NOREF#795  -  []  327.25 205.55 0 top
NOREF#796  -  []  332.61 288.86 0 top
NOREF#797  -  []  199.33 185.42 0 top
NOREF#798  -  []  264.29 143.19 0 top
NOREF#799  -  []  284.36 272.1 90 top
NOREF#800  -  []  201.91 145.63 90 top
NOREF#801  -  []  314.33 168.13 90 top
NOREF#802  -  []  252.51 204.35 90 top
NOREF#803  -  []  263.31 164.72 0 top
NOREF#804  -  []  310.41 246.34 90 top
NOREF#805  -  []  351.34 249.5 0 top
NOREF#806  -  []  385.19 289.12 0 top
NOREF#807  -  []  108.27 171.02 0 top
NOREF#808  -  []  182.57 226.57 90 top
NOREF#809  -  []  405.93 240.56 90 top
NOREF#810  -  []  184.89 227.17 90 top
NOREF#811  -  []  463.61 171.53 0 top
NOREF#812  -  []  271.04 189.82 0 top
NOREF#813  -  []  272.25 184.23 0 top
NOREF#814  -  []  450.03 166.93 0 top
NOREF#815  -  []  377.23 289.12 0 top
NOREF#816  -  []  284.36 280.1 0 top
NOREF#817  -  []  124.39 214.79 0 top
NOREF#818  -  []  400.85 249.11 0 top
NOREF#819  -  []  295.96 188.49 0 top
NOREF#820  -  []  182.57 254 90 top
NOREF#821  -  []  305.94 288.86 0 top
NOREF#822  -  []  330.73 265.55 0 top
NOREF#823  -  []  302.32 144.15 0 top
NOREF#824  -  []  301.34 286.96 0 top
NOREF#825  -  []  285.02 288.91 90 top
NOREF#826  -  []  449.99 174.46 0 top
NOREF#827  -  []  419.65 256.92 90 top
NOREF#828  -  []  182.57 144.78 0 top
NOREF#829  -  []  309.21 246.34 0 top
NOREF#830  -  []  201.4 254.6 90 top
NOREF#831  -  []  201.23 219.75 90 top
NOREF#832  -  []  329.6 163.52 90 top
NOREF#833  -  []  424.47 163.19 90 top
NOREF#834  -  []  182.57 171.96 90 top
NOREF#835  -  []  242.23 173.13 90 top
NOREF#836  -  []  192.47 257.6 90 top
NOREF#837  -  []  22.16 130.26 90 top
NOREF#838  -  []  379.73 287.22 90 top
NOREF#839  -  []  118.7 190.55 90 top
NOREF#840  -  []  396.28 163.69 90 top
NOREF#841  -  []  462.06 277.31 90 top
NOREF#842  -  []  380.53 217.11 0 top
NOREF#843  -  []  250.73 265.55 0 top
NOREF#844  -  []  167.7 192.32 90 top
NOREF#845  -  []  418.12 289.12 0 top
NOREF#846  -  []  465.45 273.87 90 top
NOREF#847  -  []  393.74 131.34 90 top
NOREF#848  -  []  201.23 200.54 90 top
NOREF#849  -  []  418.12 241.11 0 top
NOREF#850  -  []  394.05 223.21 0 top
NOREF#851  -  []  105.58 234.24 90 top
NOREF#852  -  []  199.33 240.28 0 top
NOREF#853  -  []  332.51 264.35 90 top
NOREF#854  -  []  303.26 139.64 0 top
NOREF#855  -  []  459.28 168.33 0 top
NOREF#856  -  []  351.34 189.5 0 top
NOREF#857  -  []  275.28 290.13 90 top
NOREF#858  -  []  109.96 238.84 0 top
NOREF#859  -  []  304.61 131.64 0 top
NOREF#860  -  []  251.94 264.65 90 top
NOREF#861  -  []  352.55 185.18 0 top
NOREF#862  -  []  221.87 295.91 0 top
NOREF#863  -  []  199.84 175.58 90 top
NOREF#864  -  []  392.24 193.43 0 top
NOREF#865  -  []  339.65 264.65 90 top
NOREF#866  -  []  300.36 177.06 0 top
NOREF#867  -  []  272.24 241.05 90 top
NOREF#868  -  []  405.93 272.66 90 top
NOREF#869  -  []  310.73 246.66 0 top
NOREF#870  -  []  184.47 200.54 0 top
NOREF#871  -  []  310.43 247.61 0 top
